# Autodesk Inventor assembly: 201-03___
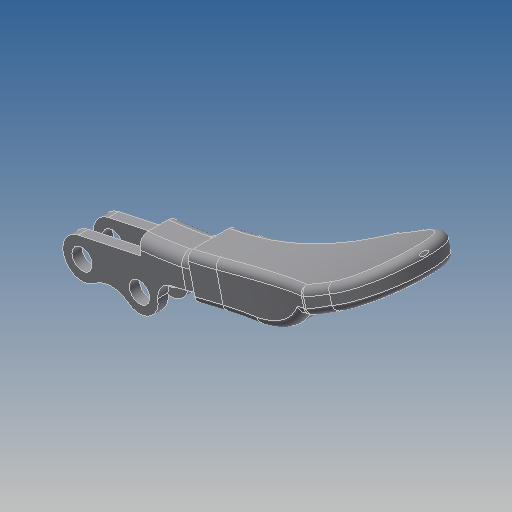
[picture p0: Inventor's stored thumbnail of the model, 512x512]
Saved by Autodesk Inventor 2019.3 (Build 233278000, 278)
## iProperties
Created: 2010-06
Part Number: 201-03___
Material: Ogólny
Document SubType Name: Assembly
Designer: CADENGINEERING4
Author: CADENGINEERING4
Revision Number: ANY
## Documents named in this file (3)
- E:\STRONA\Horizontal toggle clamp\CH-201-R\201-03___.iam
- E:\STRONA\Horizontal toggle clamp\CH-201-R\201-05___.ipt
- E:\STRONA\Horizontal toggle clamp\CH-201-R\201-A-03___.ipt
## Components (2 placed, 2 different names)
1. 201-05_??_15
2. 201-A-03_??_16
